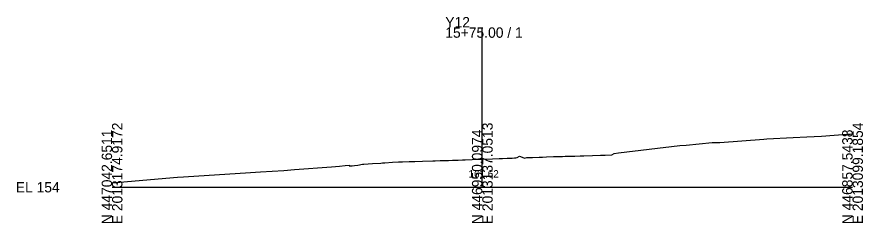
# Model space of a CAD drawing. Extents: x -26 to 1203, y -10 to 9542.
# Drawn here: x 974.3 to 1202.8, y 1490.3 to 1546.1 of the extents above; entities that cross this region are included whole.
import ezdxf

# ---------------------------------------------------------------- set-up
doc = ezdxf.new("R2010")
doc.units = 0
for name, color, linetype in [('Default', 7, 'Continuous'), ('Exist Cross Section Cell', 7, 'Continuous'), ('Exist XS Center Line Elevation Label', 7, 'Continuous'), ('Exist XS Ground Line', 7, 'Continuous')]:
    doc.layers.add(name, color=color, linetype=linetype)

msp = doc.modelspace()

# ---------------------------------------------------------------- linework, layer by layer
at = {"layer": 'Exist Cross Section Cell'}
for p, q in [((1100, 1500), (1100, 1543.22)), ((1000, 1500), (1100, 1500)), ((1100, 1500), (1200, 1500))]:
    msp.add_line(p, q, dxfattribs=at)
at = {"layer": 'Exist XS Ground Line'}
msp.add_lwpolyline([(1000, 1501.18), (1017.69, 1502.72), (1019.31, 1502.84), (1037.42, 1503.95), (1040.07, 1504.13), (1043.28, 1504.34), (1046.41, 1504.56), (1049.24, 1504.77), (1059.28, 1505.56), (1061.39, 1505.73), (1062.94, 1505.85), (1064.06, 1505.94), (1064.07, 1505.75), (1064.89, 1505.81), (1065.46, 1505.85), (1066.37, 1505.93), (1067.63, 1506.23), (1068.02, 1506.26), (1070.33, 1506.41), (1072.56, 1506.55), (1073.03, 1506.58), (1073.71, 1506.62), (1075.74, 1506.74), (1077.33, 1506.84), (1078, 1506.87), (1078.45, 1506.89), (1080.27, 1506.94), (1081.15, 1506.97), (1081.75, 1506.99), (1083.84, 1507.05), (1086.63, 1507.14), (1087.3, 1507.15), (1088.59, 1507.19), (1089.22, 1507.21), (1090.84, 1507.27), (1091.91, 1507.3), (1093.47, 1507.36), (1094.61, 1507.41), (1095.4, 1507.44), (1097.3, 1507.5), (1098.31, 1507.55), (1099.13, 1507.59), (1100.12, 1507.62), (1102.71, 1507.72), (1104.52, 1507.77), (1105.42, 1507.79), (1106.7, 1507.84), (1108.07, 1507.88), (1108.7, 1507.91), (1109.07, 1507.97), (1109.44, 1508.08), (1110.04, 1508.38), (1110.79, 1508.16), (1111.39, 1507.86), (1112.06, 1508.03), (1113.56, 1508.06), (1115.4, 1508.12), (1116.26, 1508.16), (1117.33, 1508.2), (1119.24, 1508.27), (1119.9, 1508.29), (1121.65, 1508.34), (1122.38, 1508.36), (1124.33, 1508.41), (1124.96, 1508.43), (1126.47, 1508.48), (1127.04, 1508.5), (1127.42, 1508.51), (1129.73, 1508.59), (1131.9, 1508.66), (1132.4, 1508.68), (1133.18, 1508.69), (1134.95, 1508.75), (1135.64, 1509.15), (1136.81, 1509.31), (1153.31, 1511.29), (1155.08, 1511.39), (1162.05, 1512.1), (1164.14, 1512.09), (1176, 1512.97), (1176.84, 1513.06), (1183.98, 1513.41), (1187.65, 1513.6), (1191.65, 1513.83), (1198.45, 1514.32), (1199.32, 1514.36), (1200, 1514.41)], dxfattribs=at)

# ---------------------------------------------------------------- texts
at = {"layer": 'Default'}
msp.add_text('-', height=0.0001, dxfattribs=at).set_placement((1000, 1500))
at = {"layer": 'Exist Cross Section Cell'}
for s, p in [('Y12', (1090, 1543.22)), ('15+75.00 / 1', (1090, 1540.42)), ('EL 154', (974, 1498.6))]:
    msp.add_text(s, height=2.8, dxfattribs=at).set_placement(p)
for s, p in [('N 447042.6511', (1000, 1490)), ('E 2013174.9172', (1002.8, 1490)), ('N 446950.0974', (1100, 1490)), ('E 2013137.0513', (1102.8, 1490)), ('N 446857.5438', (1200, 1490)), ('E 2013099.1854', (1202.8, 1490))]:
    msp.add_text(s, height=2.8, rotation=90, dxfattribs=at).set_placement(p)
at = {"layer": 'Exist XS Center Line Elevation Label'}
msp.add_text('161.62', height=2, dxfattribs=at).set_placement((1096.27, 1502.62))

doc.saveas('drawing.dxf')
